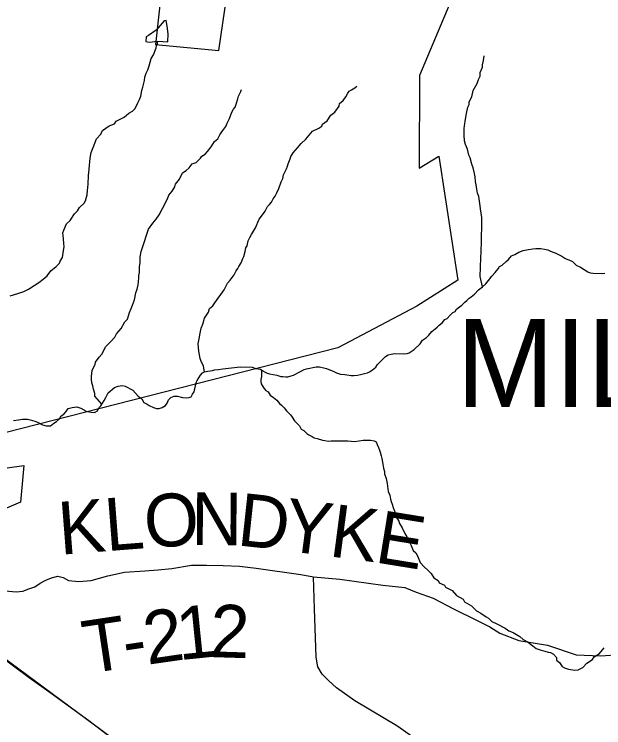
# Model space of a CAD drawing. Extents: x 44.2 to 78.2, y 4.5 to 26.5.
# Drawn here: x 51.106 to 51.74, y 21.155 to 21.923 of the extents above; entities that cross this region are included whole.
import ezdxf

# ---------------------------------------------------------------- set-up
doc = ezdxf.new("R2010")
doc.units = 0
for name, color, linetype in [('GM_X_Corporation', 7, 'Continuous'), ('GM_X_Corporation_Text', 7, 'Continuous'), ('GM_X_Minor_Lake', 7, 'Continuous'), ('GM_X_Minor_River', 7, 'Continuous'), ('GM_X_Rail_Line', 7, 'Continuous'), ('GM_X_Township_Road', 7, 'Continuous'), ('GM_X_Township_Road_Text', 7, 'Continuous'), ('GM_X_US_Route', 7, 'Continuous')]:
    doc.layers.add(name, color=color, linetype=linetype)

msp = doc.modelspace()

# ---------------------------------------------------------------- linework, layer by layer
at = {"layer": 'GM_X_Corporation'}
for points in [[(51.07438, 22.04655), (51.27263, 22.02455), (51.25807, 21.8903), (51.32619, 21.88381), (51.34566, 22.01684), (51.59487, 21.98258), (51.54217, 21.85695), (51.54188, 21.7574), (51.56296, 21.77035), (51.58328, 21.63662), (51.53924, 21.60881), (51.4542, 21.56396), (50.97735, 21.44206)], [(51.00842, 21.42212), (51.11636, 21.43729), (51.11288, 21.39756), (51.07047, 21.37955)]]:
    msp.add_lwpolyline(points, dxfattribs=at)
at = {"layer": 'GM_X_Minor_Lake'}
msp.add_lwpolyline([(51.26073, 21.89386), (51.27141, 21.89332), (51.27159, 21.90206), (51.27062, 21.91005), (51.2696, 21.91615), (51.26732, 21.91582), (51.25875, 21.90574), (51.25066, 21.90021), (51.24797, 21.89875), (51.24749, 21.89382), (51.25127, 21.89298)], dxfattribs=at)
at = {"layer": 'GM_X_Minor_River'}
for points in [[(51.25127, 21.89298), (51.26073, 21.89386)], [(51.25581, 21.8792), (51.25865, 21.88671), (51.25909, 21.88897), (51.2603, 21.8916), (51.26073, 21.89386)], [(51.10149, 21.61998), (51.10991, 21.62242), (51.11642, 21.62452), (51.12142, 21.62705), (51.1276, 21.63106), (51.13262, 21.63434), (51.13726, 21.63764), (51.14153, 21.64132), (51.14547, 21.6469), (51.15128, 21.6513), (51.15479, 21.655), (51.15561, 21.65726), (51.15798, 21.66099), (51.15893, 21.66855), (51.1598, 21.6727), (51.1595, 21.67612), (51.15887, 21.68107), (51.15858, 21.68487), (51.15827, 21.68753), (51.15949, 21.69054), (51.16232, 21.69729), (51.16621, 21.70098), (51.17095, 21.70807), (51.17407, 21.7114), (51.17644, 21.71475), (51.18112, 21.71956), (51.1827, 21.72218), (51.18394, 21.72594), (51.18438, 21.72858), (51.18488, 21.73312), (51.18534, 21.73652), (51.18543, 21.73993), (51.18605, 21.7494), (51.18659, 21.75583), (51.18709, 21.76037), (51.18756, 21.76415), (51.18766, 21.76794), (51.18895, 21.77398), (51.19099, 21.77961), (51.19465, 21.789), (51.19933, 21.79381), (51.20095, 21.79794), (51.20829, 21.80268), (51.21405, 21.80518), (51.21563, 21.8078), (51.22448, 21.81212), (51.22953, 21.81654), (51.23338, 21.81871), (51.23612, 21.82168), (51.23893, 21.82767), (51.24091, 21.83103), (51.24215, 21.8348), (51.24344, 21.84083), (51.24429, 21.8446), (51.24637, 21.85175), (51.24646, 21.85517), (51.2481, 21.85968), (51.2497, 21.86305), (51.25133, 21.86756), (51.25343, 21.87546), (51.25581, 21.8792)], [(51.60993, 21.62944), (51.60755, 21.64051), (51.60806, 21.6606), (51.6086, 21.66703), (51.6089, 21.67878), (51.60941, 21.69887), (51.60916, 21.70419), (51.60788, 21.71333), (51.60758, 21.71675), (51.60657, 21.72171), (51.60593, 21.72666), (51.60451, 21.73049), (51.60386, 21.73468), (51.60321, 21.73925), (51.60255, 21.74306), (51.60192, 21.748), (51.60124, 21.75143), (51.59988, 21.75754), (51.59847, 21.76175), (51.59673, 21.76824), (51.59529, 21.77132), (51.59393, 21.7778), (51.59178, 21.78279), (51.59074, 21.78661), (51.59013, 21.79269), (51.59033, 21.80027), (51.59076, 21.80254), (51.59083, 21.80519), (51.59127, 21.80746), (51.59171, 21.8101), (51.59263, 21.81614), (51.59432, 21.82293), (51.59553, 21.82593), (51.59559, 21.82821), (51.5972, 21.83158), (51.5984, 21.8342), (51.60009, 21.84098), (51.60408, 21.84847), (51.6057, 21.8526), (51.60732, 21.85635), (51.60742, 21.86014), (51.60985, 21.86614), (51.6099, 21.86842), (51.61117, 21.87332), (51.61167, 21.87823)], [(51.20032, 21.50321), (51.19294, 21.51175), (51.19263, 21.5148), (51.19123, 21.51938), (51.19056, 21.52282), (51.18951, 21.52626), (51.18922, 21.53006), (51.1893, 21.53309), (51.18984, 21.53953), (51.19184, 21.54327), (51.19304, 21.54589), (51.19349, 21.54853), (51.19742, 21.55375), (51.20017, 21.55709), (51.20455, 21.56532), (51.21, 21.57049), (51.2143, 21.5753), (51.21591, 21.57906), (51.22099, 21.58461), (51.22497, 21.59172), (51.22808, 21.59467), (51.23017, 21.60182), (51.2318, 21.60633), (51.2334, 21.60971), (51.23545, 21.61534), (51.23678, 21.62289), (51.2384, 21.62702), (51.23927, 21.63155), (51.24022, 21.63874), (51.24029, 21.64177), (51.24075, 21.64479), (51.24091, 21.65124), (51.2414, 21.6554), (51.24156, 21.66184), (51.24246, 21.6675), (51.2441, 21.67201), (51.25067, 21.69157), (51.25501, 21.6979), (51.25892, 21.70235), (51.26208, 21.7072), (51.26567, 21.71394), (51.27088, 21.72442), (51.27249, 21.72817), (51.27602, 21.73263), (51.27879, 21.73711), (51.27963, 21.74012), (51.28394, 21.74532), (51.28715, 21.75207), (51.29101, 21.75462), (51.29413, 21.75757), (51.29766, 21.76203), (51.30187, 21.76344), (51.30654, 21.76787), (51.30774, 21.77011), (51.31159, 21.77229), (51.31394, 21.77526), (51.31786, 21.78009), (51.32143, 21.78607), (51.32531, 21.789), (51.32731, 21.79312), (51.32889, 21.79535), (51.33047, 21.79797), (51.33361, 21.80206), (51.33523, 21.80581), (51.33763, 21.81068), (51.34008, 21.81744), (51.34206, 21.8208), (51.34364, 21.82304), (51.34486, 21.82604), (51.34653, 21.83207), (51.34735, 21.8347), (51.34855, 21.83694), (51.34977, 21.83995), (51.35047, 21.8419)], [(51.31096, 21.53788), (51.3096, 21.54398), (51.30672, 21.55013), (51.30602, 21.55242), (51.30535, 21.55623), (51.3047, 21.56042), (51.30413, 21.56802), (51.30504, 21.57369), (51.30595, 21.57973), (51.30722, 21.58501), (51.30885, 21.58914), (51.31092, 21.59592), (51.31526, 21.60225), (51.31611, 21.60602), (51.3196, 21.60896), (51.32197, 21.61232), (51.32551, 21.61716), (51.32827, 21.62126), (51.33181, 21.6261), (51.33542, 21.63359), (51.33853, 21.63654), (51.34286, 21.6425), (51.34487, 21.64662), (51.34683, 21.64922), (51.34765, 21.65148), (51.3504, 21.6552), (51.35205, 21.66009), (51.35324, 21.66233), (51.35451, 21.66761), (51.35537, 21.67138), (51.35657, 21.67363), (51.35784, 21.6789), (51.35945, 21.68265), (51.36144, 21.68602), (51.3658, 21.69311), (51.36945, 21.7025), (51.37336, 21.70695), (51.37613, 21.71105), (51.37853, 21.71591), (51.38086, 21.71813), (51.38283, 21.72073), (51.38481, 21.7241), (51.38679, 21.72708), (51.38878, 21.73082), (51.3908, 21.73532), (51.39326, 21.74246), (51.39525, 21.7462), (51.39573, 21.74999), (51.39893, 21.75673), (51.40014, 21.75935), (51.40097, 21.76199), (51.403, 21.76724), (51.40382, 21.76988), (51.4062, 21.77361), (51.40854, 21.7762), (51.4109, 21.77918), (51.41482, 21.784), (51.41987, 21.78842), (51.42692, 21.79696), (51.43384, 21.8002), (51.43693, 21.80239), (51.43775, 21.80464), (51.44278, 21.80831), (51.44673, 21.81427), (51.45099, 21.81757), (51.45571, 21.8239), (51.45617, 21.82692), (51.46005, 21.83024), (51.4628, 21.83396), (51.46518, 21.83807), (51.46638, 21.84031), (51.46908, 21.84176), (51.47255, 21.84394), (51.47486, 21.8454)], [(51.41352, 21.53785), (51.41814, 21.54038), (51.42043, 21.54108), (51.43113, 21.54346), (51.43455, 21.54337), (51.4421, 21.54165), (51.44999, 21.53841), (51.45299, 21.53682), (51.45714, 21.53557), (51.46168, 21.53507), (51.46849, 21.53413), (51.47153, 21.53405), (51.47534, 21.53433), (51.47877, 21.535), (51.48298, 21.53603), (51.48604, 21.53709), (51.48835, 21.53817), (51.49143, 21.53998), (51.49531, 21.54292), (51.4969, 21.54591), (51.50158, 21.55072), (51.50547, 21.55441), (51.50856, 21.55623), (51.51161, 21.5569), (51.51543, 21.55756), (51.52454, 21.55732), (51.52872, 21.5576), (51.53102, 21.55829), (51.53333, 21.55975), (51.53643, 21.56195), (51.54304, 21.56822), (51.54542, 21.57195), (51.54967, 21.57488), (51.55239, 21.57746), (51.55554, 21.58155), (51.55902, 21.58411), (51.56135, 21.58595), (51.5633, 21.58818), (51.56641, 21.59075), (51.56954, 21.59446), (51.57184, 21.59554), (51.57535, 21.59886), (51.57808, 21.60182), (51.58039, 21.6029), (51.58197, 21.60552), (51.58508, 21.60809), (51.58778, 21.60992), (51.59089, 21.61287), (51.59322, 21.61471), (51.59556, 21.6173), (51.59788, 21.61876), (51.60137, 21.6217), (51.60567, 21.62614), (51.60993, 21.62944), (51.61343, 21.63277), (51.61656, 21.63648), (51.62009, 21.64094), (51.62361, 21.64502), (51.62675, 21.64873), (51.62833, 21.65134), (51.63103, 21.65279), (51.63531, 21.65685), (51.63802, 21.65906), (51.64116, 21.66277), (51.64461, 21.66419), (51.64923, 21.66673), (51.65384, 21.6685), (51.65957, 21.66987), (51.66414, 21.67051), (51.66719, 21.67081), (51.67288, 21.67066), (51.67667, 21.67018), (51.68045, 21.66932), (51.68306, 21.66774), (51.68608, 21.6669), (51.68871, 21.66569), (51.69096, 21.6645), (51.69546, 21.66248), (51.69845, 21.66051), (51.7007, 21.65931), (51.70296, 21.65849), (51.70672, 21.65688), (51.7108, 21.65298), (51.71529, 21.65058), (51.72315, 21.64583), (51.72577, 21.64462), (51.72918, 21.64415), (51.73905, 21.64389), (51.74172, 21.6442)], [(51.10529, 21.48559), (51.11063, 21.48621), (51.11482, 21.48686), (51.12014, 21.4871), (51.12316, 21.48626), (51.12807, 21.485), (51.13108, 21.48378), (51.13632, 21.48099), (51.14047, 21.47974), (51.14503, 21.48), (51.14852, 21.48257), (51.1516, 21.48438), (51.15471, 21.48734), (51.1567, 21.4907), (51.1594, 21.49252), (51.16175, 21.49512), (51.16411, 21.49847), (51.16832, 21.4995), (51.17327, 21.50013), (51.1778, 21.49887), (51.18341, 21.49569), (51.1887, 21.49441), (51.19249, 21.49432), (51.19558, 21.49613), (51.19717, 21.49912), (51.19913, 21.50135), (51.20269, 21.50695), (51.20467, 21.51031), (51.20709, 21.51556), (51.21406, 21.52106), (51.2179, 21.52248), (51.22209, 21.52313), (51.2255, 21.52266), (51.23374, 21.51827), (51.23927, 21.51168), (51.24338, 21.50892), (51.24556, 21.50507), (51.24893, 21.50308), (51.25118, 21.50188), (51.25606, 21.49948), (51.25907, 21.49864), (51.26211, 21.49856), (51.26517, 21.49962), (51.26865, 21.50181), (51.27061, 21.50441), (51.27222, 21.50778), (51.27456, 21.51038), (51.27802, 21.5118), (51.28181, 21.51171), (51.2871, 21.51043), (51.29164, 21.50993), (51.29431, 21.51024), (51.29661, 21.51094), (51.29782, 21.51394), (51.29979, 21.51654), (51.30109, 21.52296), (51.30194, 21.52635), (51.30275, 21.52861), (51.30473, 21.53159), (51.30632, 21.53458), (51.30866, 21.5368), (51.31096, 21.53788), (51.3144, 21.53854), (51.31936, 21.53955), (51.32166, 21.54025), (51.32585, 21.54052), (51.33042, 21.54116), (51.34909, 21.54333), (51.36199, 21.54299), (51.36614, 21.54174), (51.36841, 21.5413), (51.37105, 21.54086), (51.37366, 21.53889), (51.37591, 21.53769), (51.37816, 21.5365), (51.38079, 21.53567), (51.38874, 21.53432), (51.39288, 21.53308), (51.39516, 21.53302), (51.39819, 21.53256), (51.40046, 21.5325), (51.40391, 21.53355), (51.40659, 21.53424), (51.41352, 21.53785)], [(51.37204, 21.54011), (51.37199, 21.53287), (51.37153, 21.52984), (51.37148, 21.52757), (51.37179, 21.5249), (51.37471, 21.52028), (51.37693, 21.51794), (51.37917, 21.51636), (51.38136, 21.51289), (51.3851, 21.51052), (51.38881, 21.50739), (51.39138, 21.50391), (51.39361, 21.50195), (51.39658, 21.49922), (51.39916, 21.49611), (51.40323, 21.49184), (51.40506, 21.48913), (51.40762, 21.48527), (51.41096, 21.48215), (51.41318, 21.47982), (51.41499, 21.47635), (51.41761, 21.47477), (51.42095, 21.47164), (51.42319, 21.47007), (51.42657, 21.46846), (51.42881, 21.46689), (51.4322, 21.46604), (51.43786, 21.46437), (51.44013, 21.46394), (51.44429, 21.46345), (51.44696, 21.46376), (51.45379, 21.46358), (51.45798, 21.46385), (51.46519, 21.46366), (51.46859, 21.46319), (51.47201, 21.4631), (51.47734, 21.46372), (51.48154, 21.46437), (51.48533, 21.46427), (51.48952, 21.46454), (51.4933, 21.46368), (51.49554, 21.46249), (51.49662, 21.4598), (51.49805, 21.45635), (51.49912, 21.45367), (51.49982, 21.45137), (51.50086, 21.44755), (51.50154, 21.4445), (51.50253, 21.4384), (51.50356, 21.4342), (51.50461, 21.43076), (51.50455, 21.42811), (51.50632, 21.42313), (51.50732, 21.41779), (51.50862, 21.40903), (51.51042, 21.40519), (51.51107, 21.401), (51.51177, 21.39833), (51.51284, 21.39565), (51.51388, 21.39182), (51.51495, 21.38914), (51.51674, 21.38492), (51.51777, 21.38034), (51.51997, 21.37725), (51.52066, 21.37458), (51.52358, 21.36995), (51.52646, 21.3638), (51.52865, 21.36033), (51.52934, 21.35728), (51.53155, 21.35456), (51.53336, 21.3511), (51.5355, 21.34574), (51.53809, 21.34301), (51.53991, 21.33993), (51.54276, 21.33265), (51.5472, 21.32798), (51.55166, 21.32407), (51.55462, 21.32096), (51.55754, 21.31633), (51.5624, 21.31317), (51.56348, 21.31086), (51.56912, 21.30843), (51.5702, 21.30613), (51.57732, 21.30253), (51.58212, 21.29709), (51.58924, 21.29311), (51.59069, 21.29042), (51.59817, 21.28605), (51.60335, 21.2806), (51.60823, 21.2782), (51.61383, 21.27426), (51.61644, 21.27268), (51.62015, 21.26916), (51.62541, 21.26675), (51.6344, 21.26196), (51.63813, 21.25921), (51.64302, 21.25718), (51.65013, 21.25321), (51.65384, 21.24969), (51.65909, 21.2469), (51.6617, 21.24493)], [(51.6617, 21.24493), (51.66431, 21.24297), (51.66766, 21.24023), (51.67217, 21.23859), (51.67708, 21.23732), (51.68046, 21.2361), (51.68311, 21.23565), (51.68649, 21.23404), (51.68944, 21.23055), (51.68974, 21.22751), (51.69272, 21.22515), (51.69565, 21.2209), (51.69827, 21.21932), (51.70241, 21.21769), (51.70922, 21.21675), (51.71302, 21.21703), (51.71803, 21.21956), (51.72233, 21.22438), (51.72851, 21.22839), (51.73009, 21.231), (51.73588, 21.23465), (51.74098, 21.24096)]]:
    msp.add_lwpolyline(points, dxfattribs=at)
at = {"layer": 'GM_X_Rail_Line'}
msp.add_lwpolyline([(51.29185, 21.08383), (51.09313, 21.23125), (51.06249, 21.265), (50.95439, 21.40652), (50.93682, 21.41951), (50.80784, 21.48644), (50.72535, 21.51824), (50.69265, 21.54006), (50.56238, 21.63213), (50.42746, 21.75571), (50.37657, 21.79579), (50.31114, 21.83259), (50.22976, 21.86486), (49.72176, 22.06319), (49.70518, 22.06505), (49.47577, 22.02697), (49.39783, 22.00234), (49.29163, 21.93729), (49.27607, 21.90161), (49.25836, 21.85106), (49.20223, 21.70581), (49.17232, 21.65276), (49.1425, 21.61997), (49.11668, 21.59791)], dxfattribs=at)
at = {"layer": 'GM_X_Township_Road'}
for points in [[(51.09622, 21.3021), (51.10798, 21.30128), (51.1151, 21.30177), (51.12187, 21.30433), (51.12827, 21.30659), (51.13402, 21.31028), (51.14016, 21.31357), (51.14602, 21.31633), (51.15301, 21.31817), (51.15868, 21.31648), (51.1644, 21.31347), (51.17556, 21.31223), (51.18874, 21.31325), (51.20668, 21.31851), (51.22485, 21.32212), (51.2464, 21.32385), (51.26101, 21.32472), (51.27576, 21.32631), (51.29695, 21.32981), (51.31285, 21.32987), (51.33103, 21.32951), (51.34837, 21.32863), (51.3663, 21.32675), (51.41443, 21.31974), (51.42792, 21.31734), (51.45651, 21.31466), (51.50273, 21.30844), (51.52621, 21.30588), (51.53869, 21.30074), (51.55705, 21.29413), (51.5787, 21.28275), (51.60439, 21.27027), (51.61797, 21.2633), (51.62876, 21.25666), (51.64905, 21.24865), (51.68, 21.24384), (51.71092, 21.23346), (51.7371, 21.23221), (51.77941, 21.23493)], [(51.70933, 20.88216), (51.71611, 20.92142), (51.71837, 20.95191), (51.72006, 20.98156), (51.72091, 21.0067), (51.71696, 21.01602), (51.71159, 21.02138), (51.69013, 21.03551), (51.66414, 21.05427), (51.58513, 21.10933), (51.51786, 21.15693), (51.47268, 21.18379), (51.45289, 21.19786), (51.44434, 21.20564), (51.4373, 21.21262), (51.43291, 21.22031), (51.43085, 21.23061), (51.42919, 21.28289), (51.42792, 21.31734)]]:
    msp.add_lwpolyline(points, dxfattribs=at)
at = {"layer": 'GM_X_US_Route'}
msp.add_lwpolyline([(51.06326, 21.26341), (51.06675, 21.25856), (51.07635, 21.24764), (51.09126, 21.23191), (51.10649, 21.22032), (51.12221, 21.20873), (51.14572, 21.19201), (51.18645, 21.16254), (51.21972, 21.13722), (51.25234, 21.11139), (51.29009, 21.08325), (51.31161, 21.06321), (51.31856, 21.05427), (51.32419, 21.045), (51.32916, 21.03441), (51.3333, 21.02), (51.33429, 21.00146), (51.33462, 20.97679), (51.33658, 20.95529), (51.3367, 20.95432)], dxfattribs=at)

# ---------------------------------------------------------------- texts
at = {"layer": 'GM_X_Corporation_Text'}
msp.add_text('MILFORD', height=0.094697, rotation=0.00001, dxfattribs=at).set_placement((51.58178, 21.50007))
at = {"layer": 'GM_X_Township_Road_Text'}
for s, rotation, p in [('K', 4.42301, (51.15548, 21.34099)), ('L', 4.41843, (51.20533, 21.34485)), ('O', 3.94832, (51.24758, 21.34811)), ('N', 359.61021, (51.29632, 21.35152)), ('D', 353.84647, (51.34481, 21.35127)), ('Y', 352.59529, (51.3942, 21.34594)), ('K', 352.54017, (51.44377, 21.3395)), ('E', 350.77651, (51.49288, 21.33308)), ('1', 5.79655, (51.28334, 21.22746)), ('2', 358.22001, (51.31618, 21.23092)), ('2', 8.16175, (51.24931, 21.22257)), ('T', 8.53861, (51.1843, 21.21284)), ('-', 8.45357, (51.22631, 21.21915))]:
    msp.add_text(s, height=0.05682, rotation=rotation, dxfattribs=at).set_placement(p)

doc.saveas('drawing.dxf')
